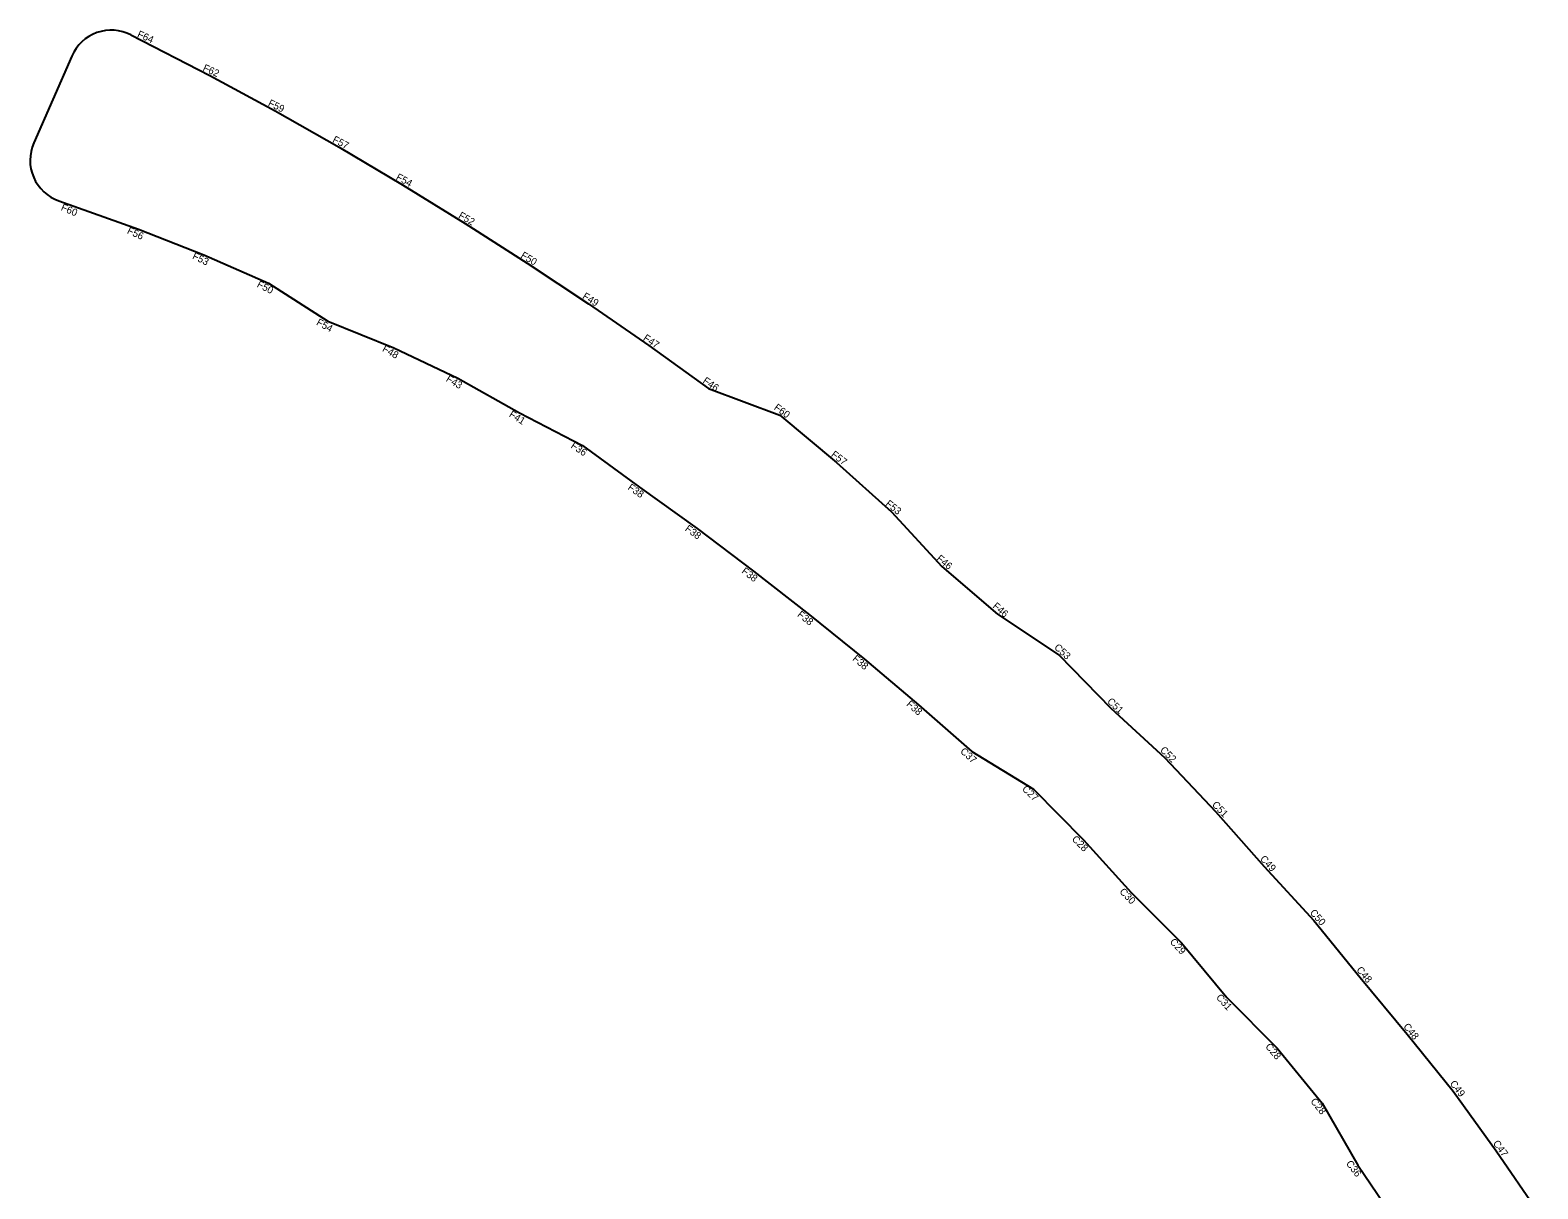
# Model space of a CAD drawing. Extents: x 2164037 to 2171931, y 206073 to 210167.
# Drawn here: x 2170456 to 2171504, y 206877 to 207682 of the extents above; entities that cross this region are included whole.
import ezdxf

# ---------------------------------------------------------------- set-up
doc = ezdxf.new("R2010")
doc.units = 0
doc.layers.add('RD_PD_CstnLmt', color=7, linetype='Continuous')
doc.layers.add('RD_PD_TX_CstnLmt', color=7, linetype='Continuous')

msp = doc.modelspace()

# ---------------------------------------------------------------- linework, layer by layer
at = {"layer": 'RD_PD_CstnLmt'}
for p, q in [((2170526.5, 207678.4), (2170581.4, 207650.2)), ((2170485.3, 207663.7), (2170458.9, 207603.3)), ((2170581.4, 207650.2), (2170626.6, 207625.7)), ((2170626.6, 207625.7), (2170671.2, 207600.4)), ((2170671.2, 207600.4), (2170715.2, 207574.2)), ((2170715.2, 207574.2), (2170758.8, 207547.3)), ((2170476.4, 207563.1), (2170531.7, 207543.5)), ((2170758.8, 207547.3), (2170801.8, 207519.7)), ((2170531.7, 207543.5), (2170577.2, 207525.5)), ((2170577.2, 207525.5), (2170622.1, 207505.9)), ((2170801.8, 207519.7), (2170844.4, 207491.5)), ((2170622.1, 207505.9), (2170663.4, 207479.4)), ((2170844.4, 207491.5), (2170886.4, 207462.5)), ((2170663.4, 207479.4), (2170709.1, 207460.9)), ((2170709.1, 207460.9), (2170753.6, 207439.9)), ((2170886.4, 207462.5), (2170927.8, 207432.6)), ((2170753.6, 207439.9), (2170796.4, 207415.8)), ((2170927.8, 207432.6), (2170977.4, 207414.1)), ((2170796.4, 207415.8), (2170840.3, 207393.2)), ((2170977.4, 207414.1), (2171016.9, 207381.3)), ((2170840.3, 207393.2), (2170880, 207364.1)), ((2171016.9, 207381.3), (2171055, 207346.9)), ((2170880, 207364.1), (2170919.9, 207335.3)), ((2171055, 207346.9), (2171090, 207309)), ((2170919.9, 207335.3), (2170959.2, 207305.7)), ((2170959.2, 207305.7), (2170998, 207275.5)), ((2171090, 207309), (2171128.8, 207276)), ((2170998, 207275.5), (2171036.3, 207244.6)), ((2171128.8, 207276), (2171171.6, 207247.3)), ((2171036.3, 207244.6), (2171073.9, 207212.9)), ((2171171.6, 207247.3), (2171207.4, 207210.6)), ((2171073.9, 207212.9), (2171110.8, 207180.4)), ((2171207.4, 207210.6), (2171244.9, 207176)), ((2171110.8, 207180.4), (2171153.8, 207154.2)), ((2171244.9, 207176), (2171280.1, 207138.8)), ((2171153.8, 207154.2), (2171188.5, 207119.1)), ((2171280.1, 207138.8), (2171314, 207100.6)), ((2171188.5, 207119.1), (2171221.7, 207082.5)), ((2171314, 207100.6), (2171348.6, 207063)), ((2171221.7, 207082.5), (2171256.6, 207047.6)), ((2171348.6, 207063), (2171380.8, 207023.4)), ((2171256.6, 207047.6), (2171288.1, 207009.5)), ((2171380.8, 207023.4), (2171413.3, 206984)), ((2171288.1, 207009.5), (2171323, 206974.4)), ((2171413.3, 206984), (2171445.4, 206944.4)), ((2171323, 206974.4), (2171354.3, 206936.2)), ((2171445.4, 206944.4), (2171475.2, 206902.9)), ((2171354.3, 206936.2), (2171379, 206892.9)), ((2171475.2, 206902.9), (2171504.2, 206860.9)), ((2171379, 206892.9), (2171406.8, 206852.2))]:
    msp.add_line(p, q, dxfattribs=at)
for centre, start, end in [((2170512.8, 207651.7), 62.8272, 156.4304), ((2170486.4, 207591.3), 156.4304, 250.4672)]:
    msp.add_arc(centre, 30, start, end, dxfattribs=at)

# ---------------------------------------------------------------- texts
at = {"layer": 'RD_PD_TX_CstnLmt'}
for s, rotation, p in [('F64', 336.2571, (2170530.4, 207677.1)), ('F62', 335.0196, (2170576, 207653.8)), ('F59', 333.7822, (2170621.3, 207629.4)), ('F57', 332.5447, (2170666.1, 207604.1)), ('F54', 331.3072, (2170710.2, 207578.1)), ('F60', 336.2571, (2170477.4, 207556.8)), ('F52', 330.0697, (2170753.6, 207551.5)), ('F56', 335.0196, (2170523.4, 207540.7)), ('F53', 333.7822, (2170568.7, 207523.1)), ('F50', 328.8322, (2170796.9, 207523.9)), ('F50', 332.5447, (2170613.6, 207503.5)), ('F49', 327.5947, (2170839.8, 207495.6)), ('F54', 331.3072, (2170654.9, 207477.2)), ('F48', 330.0697, (2170700.7, 207458.9)), ('F47', 326.3572, (2170882, 207466.6)), ('F43', 328.8322, (2170745, 207438.1)), ('F46', 325.1197, (2170923.4, 207437)), ('F60', 323.8822, (2170972.9, 207418.5)), ('F41', 327.5947, (2170788.8, 207413.5)), ('F36', 326.3572, (2170831.7, 207391.8)), ('F57', 322.6448, (2171012.6, 207385.9)), ('F38', 325.1197, (2170871.3, 207362.9)), ('F53', 321.4073, (2171050.4, 207351.8)), ('F38', 323.8822, (2170911.1, 207334.3)), ('F46', 320.1698, (2171085.9, 207313.8)), ('F38', 322.6448, (2170950.4, 207304.9)), ('F46', 318.9323, (2171124.9, 207280.8)), ('F38', 321.4073, (2170989.2, 207274.8)), ('C53', 317.6948, (2171167.7, 207252.2)), ('F38', 320.1698, (2171027.5, 207244.2)), ('F38', 318.9323, (2171065, 207212.7)), ('C51', 316.4573, (2171204.5, 207214.7)), ('C37', 317.6948, (2171102.4, 207180)), ('C52', 315.2198, (2171241.3, 207181)), ('C27', 316.4573, (2171145.4, 207153.9)), ('C51', 313.9823, (2171277.4, 207143.1)), ('C28', 315.2198, (2171180, 207119.1)), ('C49', 312.7448, (2171310.8, 207105.5)), ('C30', 313.9823, (2171213.1, 207082.7)), ('C50', 311.5073, (2171345.4, 207068.2)), ('C29', 312.7448, (2171248.1, 207047.9)), ('C48', 310.2699, (2171377.8, 207028.5)), ('C31', 311.5073, (2171280.3, 207009.3)), ('C48', 309.0324, (2171410.4, 206989.2)), ('C28', 310.2699, (2171314.5, 206975.2)), ('C49', 307.7949, (2171442.7, 206949.6)), ('C28', 309.0324, (2171345.9, 206937.2)), ('C47', 306.5574, (2171472.7, 206908.1)), ('C36', 307.7949, (2171370.6, 206894))]:
    msp.add_text(s, height=5, rotation=rotation, dxfattribs=at).set_placement(p)

doc.saveas('drawing.dxf')
